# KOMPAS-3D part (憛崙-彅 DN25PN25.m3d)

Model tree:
1. Объединить компоненты:1  (labels: СЕНС-ПФ DN25PN25)

Referenced files in D:\Савин\!СЕНСОР\3D для заказчика\!Новый перечень\СЕНС-ПФ\DN25\: СЕНС-ПФ DN25PN25.a3d
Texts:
  СЕНС-ПФ DN25PN25
  ООО НПП Сенсор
